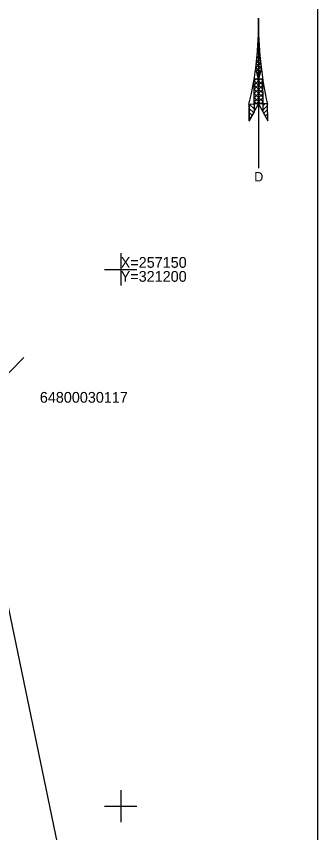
# Model space of a CAD drawing. Extents: x 321079 to 321220, y 257030 to 257220.
# Drawn here: x 321190.3 to 321218.3, y 257097.5 to 257173.6 of the extents above; entities that cross this region are included whole.
import ezdxf

# ---------------------------------------------------------------- set-up
doc = ezdxf.new("R2010")
doc.units = 0
for name, color, linetype in [('ELEK_VADV_ZSPR_####_#', 7, 'Continuous'), ('GEOD_ELEM_####_####_#', 7, 'Continuous'), ('GEOD_KORD_####_TKST_#', 7, 'Continuous'), ('RAMI_PLAN_####_TKST_#', 7, 'Continuous'), ('ROBZ_KADS_####_TKST_#', 7, 'Continuous'), ('ROBZ_UZMR_####_####_#', 7, 'Continuous')]:
    doc.layers.add(name, color=color, linetype=linetype)

msp = doc.modelspace()

# ---------------------------------------------------------------- linework, layer by layer
at = {"layer": 'ELEK_VADV_ZSPR_####_#'}
msp.add_line((321190.982, 257141.796), (321156.234, 257106.297), dxfattribs=at)
at = {"layer": 'GEOD_ELEM_####_####_#'}
for p, q in [((321200, 257151.5), (321200, 257150)), ((321198.5, 257150), (321200, 257150)), ((321200, 257150), (321200, 257148.5)), ((321200, 257150), (321201.5, 257150)), ((321200, 257101.5), (321200, 257100)), ((321198.5, 257100), (321200, 257100)), ((321200, 257100), (321200, 257098.5)), ((321200, 257100), (321201.5, 257100))]:
    msp.add_line(p, q, dxfattribs=at)
at = {"layer": 'RAMI_PLAN_####_TKST_#'}
for p, q in [((321212.801, 257173.406), (321212.801, 257159.435)), ((321212.779, 257171.313), (321212.842, 257171.371)), ((321212.781, 257171.335), (321212.846, 257171.274)), ((321212.805, 257171.705), (321212.827, 257171.683)), ((321212.733, 257170.495), (321212.879, 257170.629)), ((321212.741, 257170.595), (321212.895, 257170.453)), ((321212.759, 257170.904), (321212.861, 257171.003)), ((321212.761, 257170.968), (321212.869, 257170.865)), ((321212.615, 257169.218), (321212.971, 257169.554)), ((321212.649, 257169.521), (321213.003, 257169.184)), ((321212.665, 257169.651), (321212.939, 257169.913)), ((321212.685, 257169.877), (321212.965, 257169.609)), ((321212.7, 257170.075), (321212.909, 257170.272)), ((321212.713, 257170.237), (321212.931, 257170.031)), ((321212.567, 257168.779), (321213.002, 257169.195)), ((321212.571, 257168.821), (321212.985, 257168.425)), ((321212.609, 257169.17), (321213.053, 257168.747)), ((321212.628, 257168.448), (321213.043, 257168.848)), ((321212.648, 257168.359), (321212.904, 257168.113)), ((321212.7, 257168.131), (321212.977, 257168.394)), ((321212.412, 257166.785), (321213.199, 257167.532)), ((321212.414, 257167.174), (321213.014, 257167.744)), ((321212.419, 257167.565), (321212.605, 257167.744)), ((321212.419, 257167.552), (321213.201, 257166.808)), ((321212.626, 257167.744), (321213.201, 257167.197)), ((321212.762, 257167.858), (321212.822, 257167.801)), ((321212.773, 257167.813), (321212.844, 257167.883)), ((321213.034, 257167.744), (321213.199, 257167.586)), ((321212.403, 257165.998), (321213.201, 257166.759)), ((321212.408, 257166.392), (321213.201, 257167.146)), ((321212.412, 257166.785), (321213.202, 257166.03)), ((321212.414, 257167.165), (321213.202, 257166.42)), ((321212.4, 257165.607), (321213.202, 257166.37)), ((321212.403, 257166.014), (321213.029, 257165.42)), ((321212.408, 257166.398), (321213.205, 257165.641)), ((321212.61, 257165.42), (321213.202, 257165.981)), ((321211.931, 257165.386), (321211.953, 257163.837)), ((321211.934, 257165.386), (321212.398, 257164.95)), ((321211.937, 257164.995), (321212.365, 257164.594)), ((321211.953, 257163.837), (321212.814, 257165.41)), ((321212.312, 257165.415), (321212.399, 257165.333)), ((321212.4, 257165.627), (321212.62, 257165.42)), ((321212.814, 257165.41), (321213.671, 257163.837)), ((321213.016, 257165.42), (321213.205, 257165.596)), ((321213.202, 257164.838), (321213.653, 257165.264)), ((321213.205, 257165.226), (321213.401, 257165.415)), ((321213.671, 257163.837), (321213.649, 257165.41)), ((321211.941, 257164.602), (321212.226, 257164.337)), ((321211.948, 257164.207), (321212.085, 257164.078)), ((321213.291, 257164.531), (321213.656, 257164.883)), ((321213.43, 257164.278), (321213.661, 257164.497)), ((321211.953, 257163.844), (321211.962, 257163.852)), ((321213.57, 257164.023), (321213.668, 257164.113)), ((321213.671, 257163.839), (321213.671, 257163.839))]:
    msp.add_line(p, q, dxfattribs=at)
for points in [[(321079.019, 257029.866), (321079.019, 257219.866), (321218.314, 257219.866), (321218.314, 257029.866)], [(321212.8, 257167.704), (321212.56, 257168.736), (321212.67, 257169.692), (321212.74, 257170.566), (321212.802, 257171.705), (321212.823, 257171.705), (321212.879, 257170.629), (321212.995, 257169.26), (321213.057, 257168.711)], [(321212.42, 257167.744), (321213.199, 257167.744), (321213.205, 257165.417), (321212.399, 257165.422)], [(321212.399, 257165.422), (321212.396, 257164.648), (321211.953, 257163.837), (321211.931, 257165.386)], [(321213.205, 257165.417), (321213.202, 257164.688), (321213.671, 257163.837), (321213.649, 257165.41)]]:
    msp.add_lwpolyline(points, close=True, dxfattribs=at)
for centre, major_axis, start_param, end_param in [((321180.468, 257172.522), (32.345, 0), 6.048896, 6.311872), ((321251.139, 257173.038), (-38.341, 0), 6.273156, 6.494161)]:
    msp.add_ellipse(centre, major_axis=major_axis, ratio=0.950423, start_param=start_param, end_param=end_param, dxfattribs=at)
at = {"layer": 'ROBZ_UZMR_####_####_#'}
msp.add_line((321194.114, 257096.554), (321182.887, 257150.703), dxfattribs=at)

# ---------------------------------------------------------------- texts
at = {"layer": 'GEOD_KORD_####_TKST_#'}
for s, p in [('X=257150', (321200, 257150.15)), ('Y=321200', (321200, 257148.85))]:
    msp.add_text(s, height=1, dxfattribs=at).set_placement(p)
at = {"layer": 'RAMI_PLAN_####_TKST_#'}
msp.add_text('D', height=0.878, rotation=360, dxfattribs=at).set_placement((321212.413, 257158.193))
at = {"layer": 'ROBZ_KADS_####_TKST_#'}
msp.add_text('64800030117', height=1, dxfattribs=at).set_placement((321192.481, 257137.582))

doc.saveas('drawing.dxf')
